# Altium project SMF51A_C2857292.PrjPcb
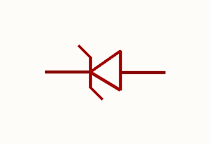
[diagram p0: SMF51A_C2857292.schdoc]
1 sheet, 1 parts. Net scope: global (net labels, ports and power ports of the same name join across sheets).

## Sheet SMF51A_C2857292.schdoc
size 127 x 101 mm

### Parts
D?  smf51a_c2857292  [SOD-123FL_L2.8-W1.8-LS3.8-RD]  (value not drawn)

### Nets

Not connected (* = marked no-connect by the designer): D? 1(C) 2(A)

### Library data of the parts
D? = smf51a_c2857292: 极性:单向;反向截止电压(Vrwm):51V;钳位电压:82.4V;峰值脉冲电流(Ipp):2.4A;峰值脉冲功率(Ppp):200W@10/1000us;击穿电压(VBR):56.7V;; Manufacturer: JSMSEMI(杰盛微); ManufacturerPart: SMF51A; AddInBom: yes; ModelId: c9a38256a2424d8b9727054099342ef3; ModelTransform: 141.732,70.866,0,0,0,0,0,0,0; Polarity: 单向; Reverse Stand-Off Voltage (Vrwm): 51V; Clamping Voltage: 82.4V; Peak Pulse Current (Ipp): 2.4A; Voltage - Breakdown: 56.7V; Reverse Leakage Current (Ir): 1uA; Number of Channels: 单路; Type: TVS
